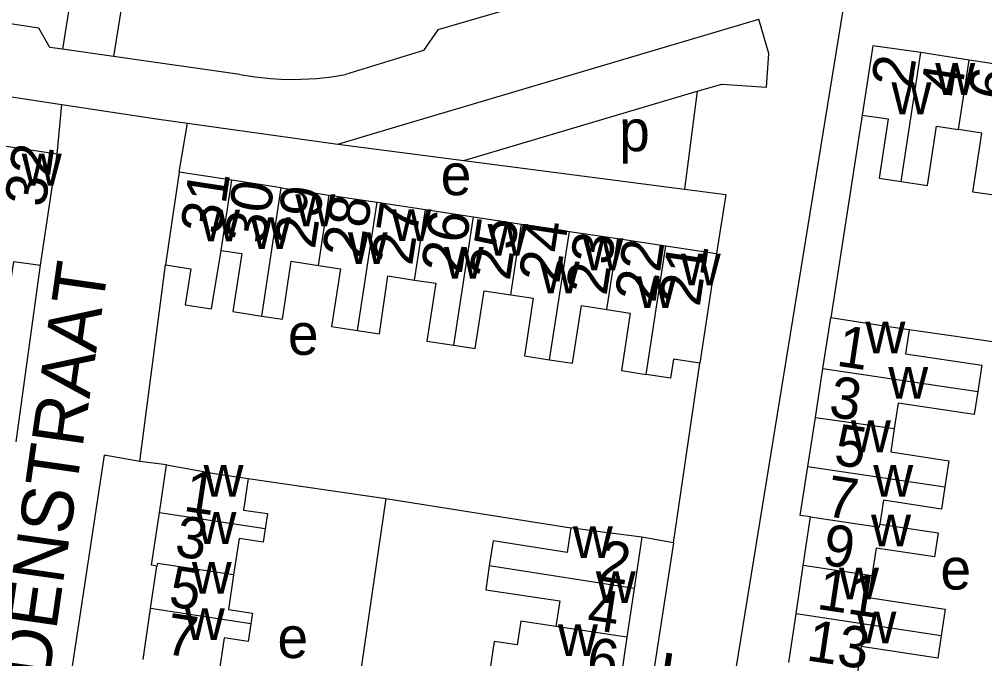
# Model space of a CAD drawing. Extents: x 161775 to 163181, y 382878 to 383925.
# Drawn here: x 162975.8 to 163069.3, y 383219.3 to 383281.3 of the extents above; entities that cross this region are included whole.
import ezdxf

# ---------------------------------------------------------------- set-up
doc = ezdxf.new("R2010")
doc.units = 0
for name, color, linetype in [('BLT_Basislijn', 7, 'Continuous'), ('BLT_Bebouwing', 7, 'Continuous'), ('BLT_Centroide', 7, 'Continuous'), ('BLT_Huisnummer', 7, 'Continuous'), ('BLT_Huisnummer_ tussenligend', 7, 'Continuous'), ('BLT_Onderverdeling_panden', 7, 'Continuous'), ('BLT_Straatnaam', 7, 'Continuous'), ('BLT_Vlakafsluiter', 7, 'Continuous')]:
    doc.layers.add(name, color=color, linetype=linetype)

msp = doc.modelspace()

# ---------------------------------------------------------------- linework, layer by layer
at = {"layer": 'BLT_Basislijn'}
for p, q in [((163051.549, 383257.313), (163055.58, 383282.143)), ((162984.928, 383277.668), (162979.977, 383278.376)), ((162997.165, 383275.919), (162984.928, 383277.668)), ((163041.456, 383274.294), (163040.203, 383264.823)), ((162979.461, 383268.217), (162979.925, 383273.009)), ((162991.274, 383266.454), (162992.08, 383271.198)), ((162992.08, 383271.198), (163006.646, 383269.184)), ((162975.49, 383240.339), (162977.859, 383257.448)), ((162987.456, 383238.448), (162989.937, 383257.483)), ((163039.192, 383181.21), (163051.549, 383257.313)), ((163072.132, 383249.729), (163061.968, 383251.187)), ((163039.163, 383230.566), (163041.692, 383247.97)), ((162990.06, 383238.111), (162987.456, 383238.448)), ((162997.958, 383236.789), (163011.305, 383234.864)), ((163011.305, 383234.864), (163029.217, 383232.022)), ((163039.163, 383230.566), (163024.222, 383134.684)), ((163039.163, 383230.566), (163036.097, 383231.121))]:
    msp.add_line(p, q, dxfattribs=at)
for points in [[(162995.33, 383301.582), (162993.496, 383293.489), (162981.796, 383289.743), (162979.977, 383278.376)], [(163000.149, 383300.226), (162997.742, 383289.599), (162986.248, 383285.919), (162984.928, 383277.668)], [(163036.749, 383285.975), (163036.44, 383286.129), (163016.338, 383280.251), (163014.947, 383278.24), (163007.37, 383275.919)], [(162979.977, 383278.376), (162978.765, 383278.549), (162977.682, 383280.405), (162946.448, 383285.201), (162944.129, 383283.654), (162941.191, 383284.273)], [(163006.646, 383269.184), (163012.256, 383270.867), (163047.401, 383281.267)], [(163041.456, 383274.294), (163043.827, 383274.995), (163048.168, 383274.703), (163048.386, 383277.94), (163047.401, 383281.267)], [(162924.815, 383278.444), (162936.334, 383279.656), (162979.925, 383273.009)], [(162997.165, 383275.919), (162998.634, 383275.684), (163000.113, 383275.528), (163001.598, 383275.452), (163003.085, 383275.456), (163004.57, 383275.54), (163006.049, 383275.704), (163007.37, 383275.919)], [(163018.836, 383267.6), (163041.456, 383274.294)], [(163057.42, 383271.972), (163054.383, 383252.342)], [(163006.646, 383269.184), (163018.836, 383267.6)], [(163018.836, 383267.6), (163040.203, 383264.823)], [(163040.203, 383264.823), (163044.228, 383264.3), (163043.302, 383258.58)], [(162987.456, 383238.448), (162984.027, 383239.066), (162976.77, 383191.371), (162976.714, 383190.883)], [(163011.305, 383234.864), (163004.347, 383187.234), (163004.27, 383186.705)]]:
    msp.add_lwpolyline(points, dxfattribs=at)
at = {"layer": 'BLT_Bebouwing'}
for p, q in [((163067.792, 383277.326), (163063.119, 383278.039)), ((163072.552, 383276.6), (163067.792, 383277.326)), ((162979.461, 383268.217), (162974.507, 383268.963)), ((162977.859, 383257.448), (162979.461, 383268.217)), ((162996.382, 383265.68), (162991.274, 383266.454)), ((163001.154, 383264.956), (162996.382, 383265.68)), ((163001.154, 383264.956), (163005.81, 383264.252)), ((163005.81, 383264.252), (163010.466, 383263.548)), ((163010.466, 383263.548), (163015.122, 383262.843)), ((163015.122, 383262.843), (163019.778, 383262.139)), ((163019.778, 383262.139), (163024.435, 383261.434)), ((163024.435, 383261.434), (163029.091, 383260.73)), ((163029.091, 383260.73), (163033.747, 383260.025)), ((163033.747, 383260.025), (163038.403, 383259.321)), ((163038.403, 383259.321), (163043.302, 383258.58)), ((163043.302, 383258.58), (163041.692, 383247.97)), ((163052.897, 383242.713), (163053.629, 383247.456)), ((163052.164, 383237.969), (163052.897, 383242.713)), ((162989.357, 383233.481), (162990.06, 383238.111)), ((162988.586, 383228.399), (162989.357, 383233.481)), ((163051.721, 383228.377), (163052.42, 383233.078)), ((163036.097, 383231.121), (163035.35, 383226.153)), ((162988.503, 383224.2), (162989.125, 383228.318)), ((162989.125, 383228.318), (162988.586, 383228.399)), ((163051.021, 383223.678), (163051.721, 383228.377)), ((163035.35, 383226.153), (163034.641, 383221.439)), ((162987.783, 383219.26), (162988.503, 383224.2)), ((163050.321, 383218.978), (163051.021, 383223.678)), ((163034.641, 383221.439), (163033.933, 383216.725))]:
    msp.add_line(p, q, dxfattribs=at)
for points in [[(163063.119, 383278.039), (163058.461, 383278.691), (163057.42, 383271.972)], [(163057.42, 383271.972), (163059.934, 383271.63), (163059.059, 383265.895), (163061.214, 383265.566)], [(163061.214, 383265.566), (163063.752, 383265.179), (163064.627, 383270.914), (163066.764, 383270.588)], [(163070.683, 383264.157), (163068.148, 383264.531), (163069.02, 383270.244), (163066.764, 383270.588)], [(162991.274, 383266.454), (162990.26, 383259.714), (162989.937, 383257.483)], [(162989.937, 383257.483), (162992.399, 383257.113), (162991.862, 383253.62), (162994.408, 383253.228), (162995.351, 383258.876)], [(162995.351, 383258.876), (162997.339, 383258.572), (162996.476, 383252.96), (162999.273, 383252.529)], [(162972.609, 383256.44), (162974.997, 383256.078), (162975.258, 383257.805), (162977.859, 383257.448)], [(162999.273, 383252.529), (163001.273, 383252.226), (163002.137, 383257.84), (163004.762, 383257.438)], [(163004.762, 383257.438), (163006.894, 383257.113), (163006.03, 383251.504), (163008.554, 383251.121)], [(163008.554, 383251.121), (163010.663, 383250.801), (163011.487, 383256.411), (163014.073, 383256.016)], [(163014.073, 383256.016), (163016.135, 383255.701), (163015.274, 383250.101), (163017.866, 383249.708)], [(163017.866, 383249.708), (163019.949, 383249.392), (163020.81, 383254.987), (163023.383, 383254.594)], [(163023.383, 383254.594), (163025.568, 383254.26), (163024.708, 383248.67), (163027.133, 383248.302)], [(163027.133, 383248.302), (163029.378, 383247.961), (163030.237, 383253.547), (163032.7, 383253.171)], [(163032.7, 383253.171), (163034.965, 383252.825), (163034.531, 383250), (163034.107, 383247.244), (163036.489, 383246.879)], [(163053.629, 383247.456), (163054.383, 383252.342)], [(163061.968, 383251.187), (163059.141, 383251.608), (163054.383, 383252.342)], [(163061.968, 383251.187), (163061.62, 383248.887), (163069.008, 383247.769), (163068.623, 383245.224)], [(163041.692, 383247.97), (163039.15, 383248.361), (163038.866, 383246.513), (163036.489, 383246.879)], [(163068.623, 383245.224), (163068.284, 383242.989), (163060.908, 383244.097), (163060.537, 383241.631)], [(163060.537, 383241.631), (163060.189, 383239.369), (163065.825, 383238.517), (163065.445, 383235.993)], [(162990.06, 383238.111), (162994.898, 383237.251), (162997.958, 383236.789)], [(163052.42, 383233.078), (163051.432, 383233.224), (163052.164, 383237.969)], [(162997.958, 383236.789), (162997.499, 383233.747), (162999.826, 383233.395), (162999.606, 383231.933)], [(163065.445, 383235.993), (163065.12, 383233.837), (163059.484, 383234.688), (163059.142, 383232.372)], [(162999.606, 383231.933), (162999.41, 383230.634), (162997.082, 383230.986), (162996.549, 383227.454)], [(163029.217, 383232.022), (163028.855, 383229.632), (163021.678, 383230.762), (163021.315, 383228.352)], [(163036.097, 383231.121), (163031.035, 383231.747), (163029.217, 383232.022)], [(163059.142, 383232.372), (163064.772, 383231.521), (163064.423, 383229.201), (163058.787, 383230.053), (163058.372, 383227.375)], [(163021.315, 383228.352), (163020.966, 383226.03), (163028.145, 383224.943), (163027.771, 383222.474)], [(162996.549, 383227.454), (162996.045, 383224.123), (162998.373, 383223.772), (162998.216, 383222.733)], [(163058.372, 383227.375), (163058.053, 383225.265), (163065.464, 383224.144), (163065.074, 383221.562)], [(162998.216, 383222.733), (162997.956, 383221.01), (162995.628, 383221.362), (162995.136, 383218.098)], [(163027.771, 383222.474), (163024.354, 383222.989), (163024.005, 383220.677), (163021.785, 383221.013), (163021.421, 383218.61)], [(163065.074, 383221.562), (163064.748, 383219.413), (163057.34, 383220.527), (163056.957, 383217.979)]]:
    msp.add_lwpolyline(points, dxfattribs=at)
at = {"layer": 'BLT_Onderverdeling_panden'}
for p, q in [((163061.214, 383265.566), (163063.119, 383278.039)), ((163066.764, 383270.588), (163067.792, 383277.326)), ((162995.351, 383258.876), (162996.382, 383265.68)), ((162999.273, 383252.529), (163001.154, 383264.956)), ((163004.762, 383257.438), (163005.81, 383264.252)), ((163008.554, 383251.121), (163010.466, 383263.548)), ((163014.073, 383256.016), (163015.122, 383262.843)), ((163017.866, 383249.708), (163019.778, 383262.139)), ((163023.383, 383254.594), (163024.435, 383261.434)), ((163027.133, 383248.302), (163029.091, 383260.73)), ((163032.7, 383253.171), (163033.747, 383260.025)), ((163036.489, 383246.879), (163038.403, 383259.321)), ((163053.629, 383247.456), (163068.623, 383245.224)), ((163052.897, 383242.713), (163060.537, 383241.631)), ((163052.164, 383237.969), (163065.445, 383235.993)), ((162999.606, 383231.933), (162989.357, 383233.481)), ((163035.35, 383226.153), (163021.315, 383228.352)), ((163058.372, 383227.375), (163051.721, 383228.377)), ((163065.074, 383221.562), (163051.021, 383223.678)), ((163034.641, 383221.439), (163027.771, 383222.474))]:
    msp.add_line(p, q, dxfattribs=at)
for points in [[(163052.42, 383233.078), (163059.098, 383232.072), (163059.142, 383232.372)], [(162996.549, 383227.454), (162989.164, 383228.569), (162989.125, 383228.318)], [(162998.216, 383222.733), (162988.503, 383224.2)]]:
    msp.add_lwpolyline(points, dxfattribs=at)
at = {"layer": 'BLT_Vlakafsluiter'}
msp.add_lwpolyline([(162979.925, 383273.009), (162989.068, 383271.615), (162992.08, 383271.198)], dxfattribs=at)

# ---------------------------------------------------------------- texts
at = {"layer": 'BLT_Centroide'}
for s, p in [('w', (163064.5, 383273.953)), ('w', (163060.266, 383272.078)), ('p', (163033.885, 383268.494)), ('w', (162976.031, 383265.172)), ('e', (163016.605, 383264.23)), ('w', (163002.531, 383261.234)), ('w', (162993.297, 383259.75)), ('w', (163011.828, 383259.797)), ('w', (162998.219, 383259.016)), ('w', (163021.141, 383258.375)), ('w', (163007.609, 383257.578)), ('w', (163030.422, 383256.969)), ('w', (163016.922, 383256.156)), ('w', (163026.203, 383254.734)), ('w', (163039.859, 383255.5)), ('w', (163035.562, 383253.312)), ('e', (163001.808, 383248.774)), ('w', (163057.742, 383248.906)), ('w', (163059.953, 383244.531)), ('w', (163056.336, 383239.344)), ('w', (162993.641, 383235.031)), ('w', (163058.5, 383235.031)), ('w', (162992.953, 383230.469)), ('w', (163058.289, 383230.219)), ('w', (163029.406, 383229.094)), ('w', (162992.5, 383225.656)), ('e', (163065.003, 383226.043)), ('w', (163031.625, 383224.75)), ('w', (163055.18, 383225.094)), ('w', (162991.828, 383221.156)), ('w', (163056.875, 383220.844)), ('e', (163000.796, 383219.413)), ('w', (163027.961, 383219.594))]:
    msp.add_text(s, height=4, dxfattribs=at).set_placement(p)
at = {"layer": 'BLT_Huisnummer'}
for s, rotation, p in [('2', 81.32081, (163062.226, 383274.493)), ('6', 81.32542, (163071.607, 383273.286)), ('32', 81.26148, (162978.283, 383262.974)), ('31', 81.31249, (162995.315, 383260.333)), ('29', 81.31445, (163004.409, 383258.933)), ('27', 81.31838, (163013.831, 383257.336)), ('25', 81.31526, (163023.287, 383255.871)), ('23', 81.31548, (163032.658, 383254.426)), ('21', 81.43613, (163041.682, 383253.356)), ('1', 351.46276, (163054.83, 383247.735)), ('5', 351.46384, (163054.575, 383238.168)), ('1', 351.43019, (162991.594, 383233.677)), ('9', 351.43974, (163053.43, 383228.485)), ('2', 351.38811, (163031.725, 383226.948)), ('5', 351.43138, (162990.145, 383224.447)), ('13', 351.43974, (163051.909, 383219.202)), ('6', 351.39514, (163030.549, 383217.53))]:
    msp.add_text(s, height=4, rotation=rotation, dxfattribs=at).set_placement(p)
at = {"layer": 'BLT_Huisnummer_ tussenligend'}
for s, rotation, p in [('4', 81.32081, (163066.994, 383273.625)), ('30', 81.31123, (162999.612, 383259.421)), ('28', 81.31641, (163009.043, 383257.997)), ('26', 81.3133, (163018.63, 383256.512)), ('24', 81.31214, (163028.08, 383255.596)), ('22', 81.25897, (163037.383, 383253.731)), ('3', 351.46276, (163054.084, 383242.818)), ('7', 351.46384, (163053.754, 383233.181)), ('3', 351.43019, (162990.742, 383229.309)), ('11', 351.43974, (163052.929, 383224.184)), ('4', 351.38811, (163030.645, 383222.249)), ('7', 351.43138, (162989.788, 383219.836))]:
    msp.add_text(s, height=4, rotation=rotation, dxfattribs=at).set_placement(p)
at = {"layer": 'BLT_Straatnaam'}
for s, height, rotation, p in [('THEODOOR VAN THULDENSTRAAT', 5, 81.83346, (162968.231, 383144.448)), ('TERWESTENSTRAAT', 4.99991, 81.55108, (163033.405, 383151.738))]:
    msp.add_text(s, height=height, rotation=rotation, dxfattribs=at).set_placement(p)

doc.saveas('drawing.dxf')
